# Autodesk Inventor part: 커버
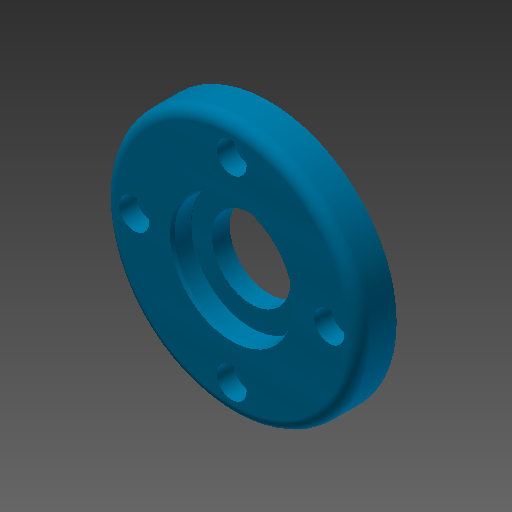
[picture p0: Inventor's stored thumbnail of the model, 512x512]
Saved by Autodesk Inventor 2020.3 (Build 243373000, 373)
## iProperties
Created: 2016-06
Part Number: 커버
Material: 알루미늄 6061
Document SubType Name: Modeling
Designer: mduedu
Density: 2.71 g/cm^3
Appearance: 하늘색 중간
Author: mduedu
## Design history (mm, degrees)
sketch "스케치1"
  geometry: C1 r 34 at (0, 0); 1 further point
  constraints: 1 centre point, 1 coincident
  dimensions: "d0" = 68 diameter of C1
extrude "돌출1" new body sketch "스케치1" distance "d2" = 10; taper "d3" = 0 deg
sketch "스케치2"
  geometry: C1 r 21 at (0, 0); 1 further point
  constraints: 1 centre point, 1 coincident
  dimensions: "d4" = 42 diameter of C1
extrude "돌출2" join sketch "스케치2" distance "d6" = 3; taper "d7" = 0 deg
fillet "모깎기1" dims "d8" = 3
hole "구멍1" diameter "d11" = 35; stored, may be unused: countersink angle "d15" = 90 deg, drill point angle "d17" = 0 deg; dims "d9" = 10, "d10" = 10, "d12" = 6, "d13" = 4, "d14" = 2, "d16" = 3
hole "구멍2" diameter "d20" = 32; stored, may be unused: countersink angle "d24" = 90 deg, drill point angle "d26" = 0 deg; dims "d21" = 6, "d22" = 4, "d23" = 2, "d25" = 5.2, "d46" = 10, "d47" = 10
hole "구멍3" diameter "d29" = 21; stored, may be unused: countersink angle "d33" = 90 deg, drill point angle "d35" = 0 deg; dims "d27" = 10, "d28" = 10, "d30" = 6, "d31" = 4, "d32" = 2, "d34" = 5
fillet "모깎기2" dims "d36" = 3
fillet "모깎기3" dims "d37" = 0.1
chamfer "모따기1" distance "d38" = 0.75; stored, may be unused: second distance "d39" = 2, angle "d40" = 30 deg
chamfer "모따기2" distance "d42" = 0.5; stored, may be unused: second distance "d43" = 2, angle "d44" = 30 deg
sketch "스케치3" dims "d48" = 52
  geometry: 6 further points
  constraints: 2 vertical alignment, 1 coincident, 7 other
  dimensions: "d51" = 360 deg dimension on point (0, 0) point (0, 26) (derived)
sketch "스케치4"
  geometry: 4 further points
hole "구멍4" sketch "스케치4" at (0, 26), (-26, 0), (0, -26), (26, 0) diameter "d53" = 4.5; stored, may be unused: countersink angle "d57" = 90 deg, drill point angle "d59" = 0 deg; dims "d54" = 6, "d55" = 8, "d56" = 4.6, "d58" = 8
node "솔리드1"
